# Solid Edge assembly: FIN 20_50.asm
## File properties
Title: Zylinder
Author: bmolnar
Template: iso assembly.asm
Last saved by: bmolnar
Revision: 16
Application: Solid Edge
Username: bmolnar
Dokumentum tartalom típus: 1
Document Number: FIN 20/50
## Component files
Kolbenstange.par
Profilrohr.par
Kit_1.par
Kit_2.par
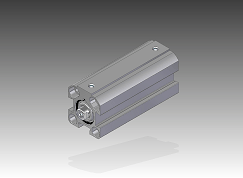
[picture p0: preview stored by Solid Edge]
